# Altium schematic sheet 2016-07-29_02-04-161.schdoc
size 331 x 127 mm; SheetNumber: 1; SheetTotal: 1
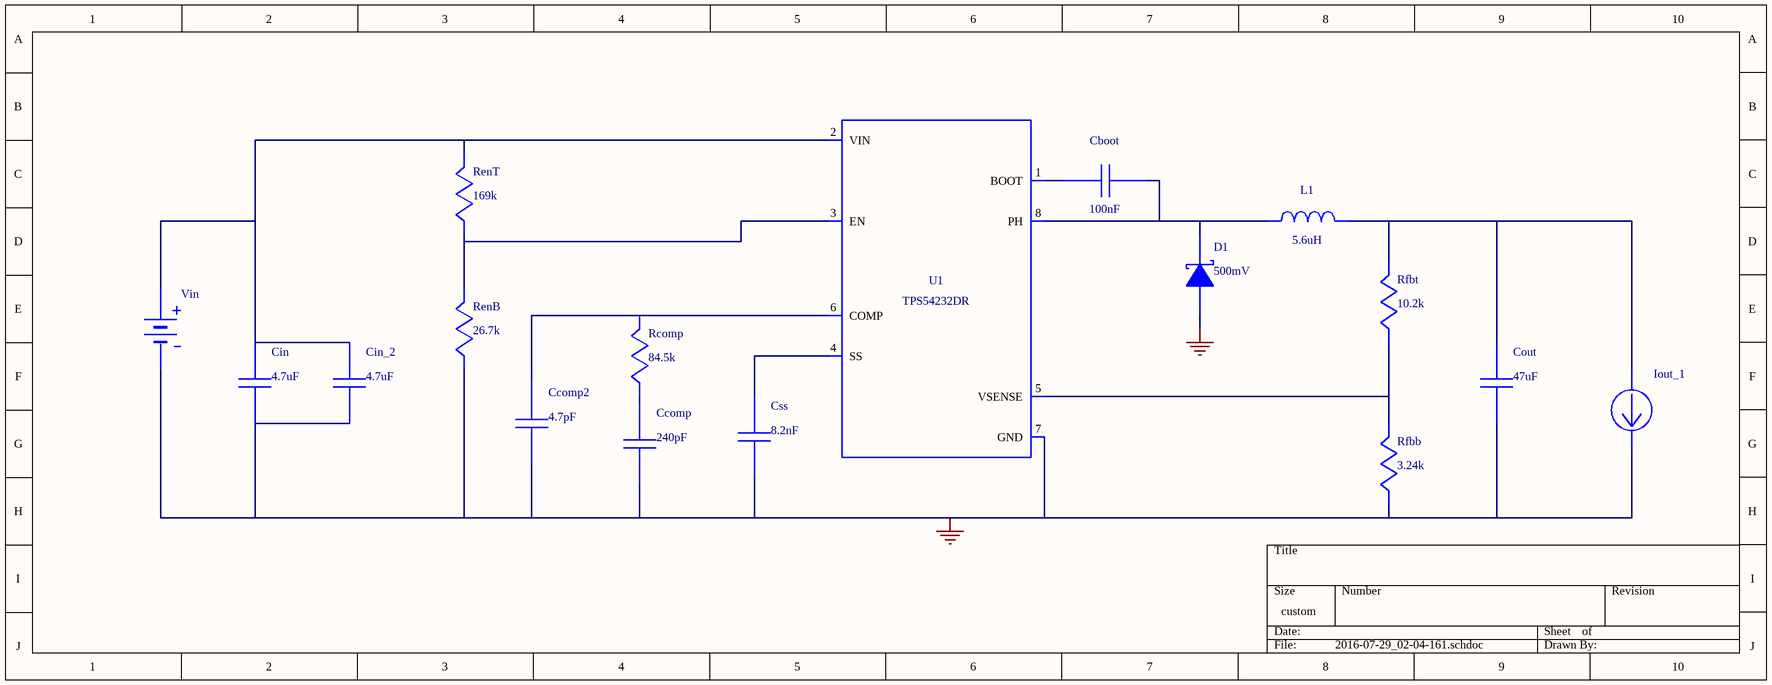
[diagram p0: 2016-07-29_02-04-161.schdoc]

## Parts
Cboot  value 100nF  (hidden comment: GRM155R61A104KA01D)
Ccomp  value 240pF  (hidden comment: GRM1555C1H241JA01D)
Ccomp2  value 4.7pF  (hidden comment: GRM1555C1H4R7CA01D)
Cin  value 4.7uF  (hidden comment: GRM32ER71H475KA88L)
Cin_2  value 4.7uF  (hidden comment: GRM32ER71H475KA88L)
Cout  value 47uF  (hidden comment: GRM31CC80J476KE18L)
Css  value 8.2nF  (hidden comment: GRM033R61A822KA01D)
D1  value 500mV  (hidden comment: B340A-13-F)
Iout_1  WB_CURRENT_LOAD  (value not drawn)
L1  value 5.6uH  (hidden comment: SDR0805-5R6ML)
Rcomp  value 84.5k  (hidden comment: CRCW040284K5FKED)
RenB  value 26.7k  (hidden comment: CRCW040226K7FKED)
RenT  value 169k  (hidden comment: CRCW0402169KFKED)
Rfbb  value 3.24k  (hidden comment: CRCW04023K24FKED)
Rfbt  value 10.2k  (hidden comment: CRCW040210K2FKED)
U1  TPS54231DR  (value not drawn)
Vin  WB_BATTERY  (value not drawn)

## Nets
0: Ccomp.2 Ccomp2.2 Cin.2 Cin_2.2 Cout.2 Css.2 D1.2(A) Iout_1.2(-) RenB.2 Rfbb.2 U1.7(GND) Vin.2(-)
NetCboot_1: Cboot.1 U1.1(BOOT)
NetCboot_2: Cboot.2 D1.1(K) L1.2 U1.8(PH)
NetCcomp2_1: Ccomp2.1 Rcomp.1 U1.6(COMP)
NetCcomp_1: Ccomp.1 Rcomp.2
NetCin_1: Cin.1 Cin_2.1 RenT.1 U1.2(VIN) Vin.1(+)
NetCout_1: Cout.1 Iout_1.1(+) L1.1 Rfbt.1
NetCss_1: Css.1 U1.4(SS)
NetRenB_1: RenB.1 RenT.2 U1.3(EN)
NetRfbb_1: Rfbb.1 Rfbt.2 U1.5(VSENSE)

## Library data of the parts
Cboot = GRM155R61A104KA01D: GRM155R61A104KA0; Manufacturer Name: MuRata
Ccomp = GRM1555C1H241JA01D: GRM1555C1H241JA0; Manufacturer Name: MuRata
Ccomp2 = GRM1555C1H4R7CA01D: GRM1555C1H4R7CA0; Manufacturer Name: MuRata
Cin Cin_2 = GRM32ER71H475KA88L: GRM32ER71H475KA8; Manufacturer Name: MuRata
Cout = GRM31CC80J476KE18L: GRM31CC80J476KE1; Manufacturer Name: MuRata
Css = GRM033R61A822KA01D: GRM033R61A822KA0; Manufacturer Name: MuRata
D1 = B340A-13-F: Manufacturer Name: Diodes Inc.
L1 = SDR0805-5R6ML: Manufacturer Name: Bourns
Rcomp = CRCW040284K5FKED: Manufacturer Name: Vishay-Dale
RenB = CRCW040226K7FKED: Manufacturer Name: Vishay-Dale
RenT = CRCW0402169KFKED: Manufacturer Name: Vishay-Dale
Rfbb = CRCW04023K24FKED: Manufacturer Name: Vishay-Dale
Rfbt = CRCW040210K2FKED: Manufacturer Name: Vishay-Dale
U1 = TPS54231DR: TPS54232DR; Manufacturer Name: Texas Instruments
